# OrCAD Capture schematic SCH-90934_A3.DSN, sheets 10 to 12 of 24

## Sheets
10 C-14 ENET1: size C
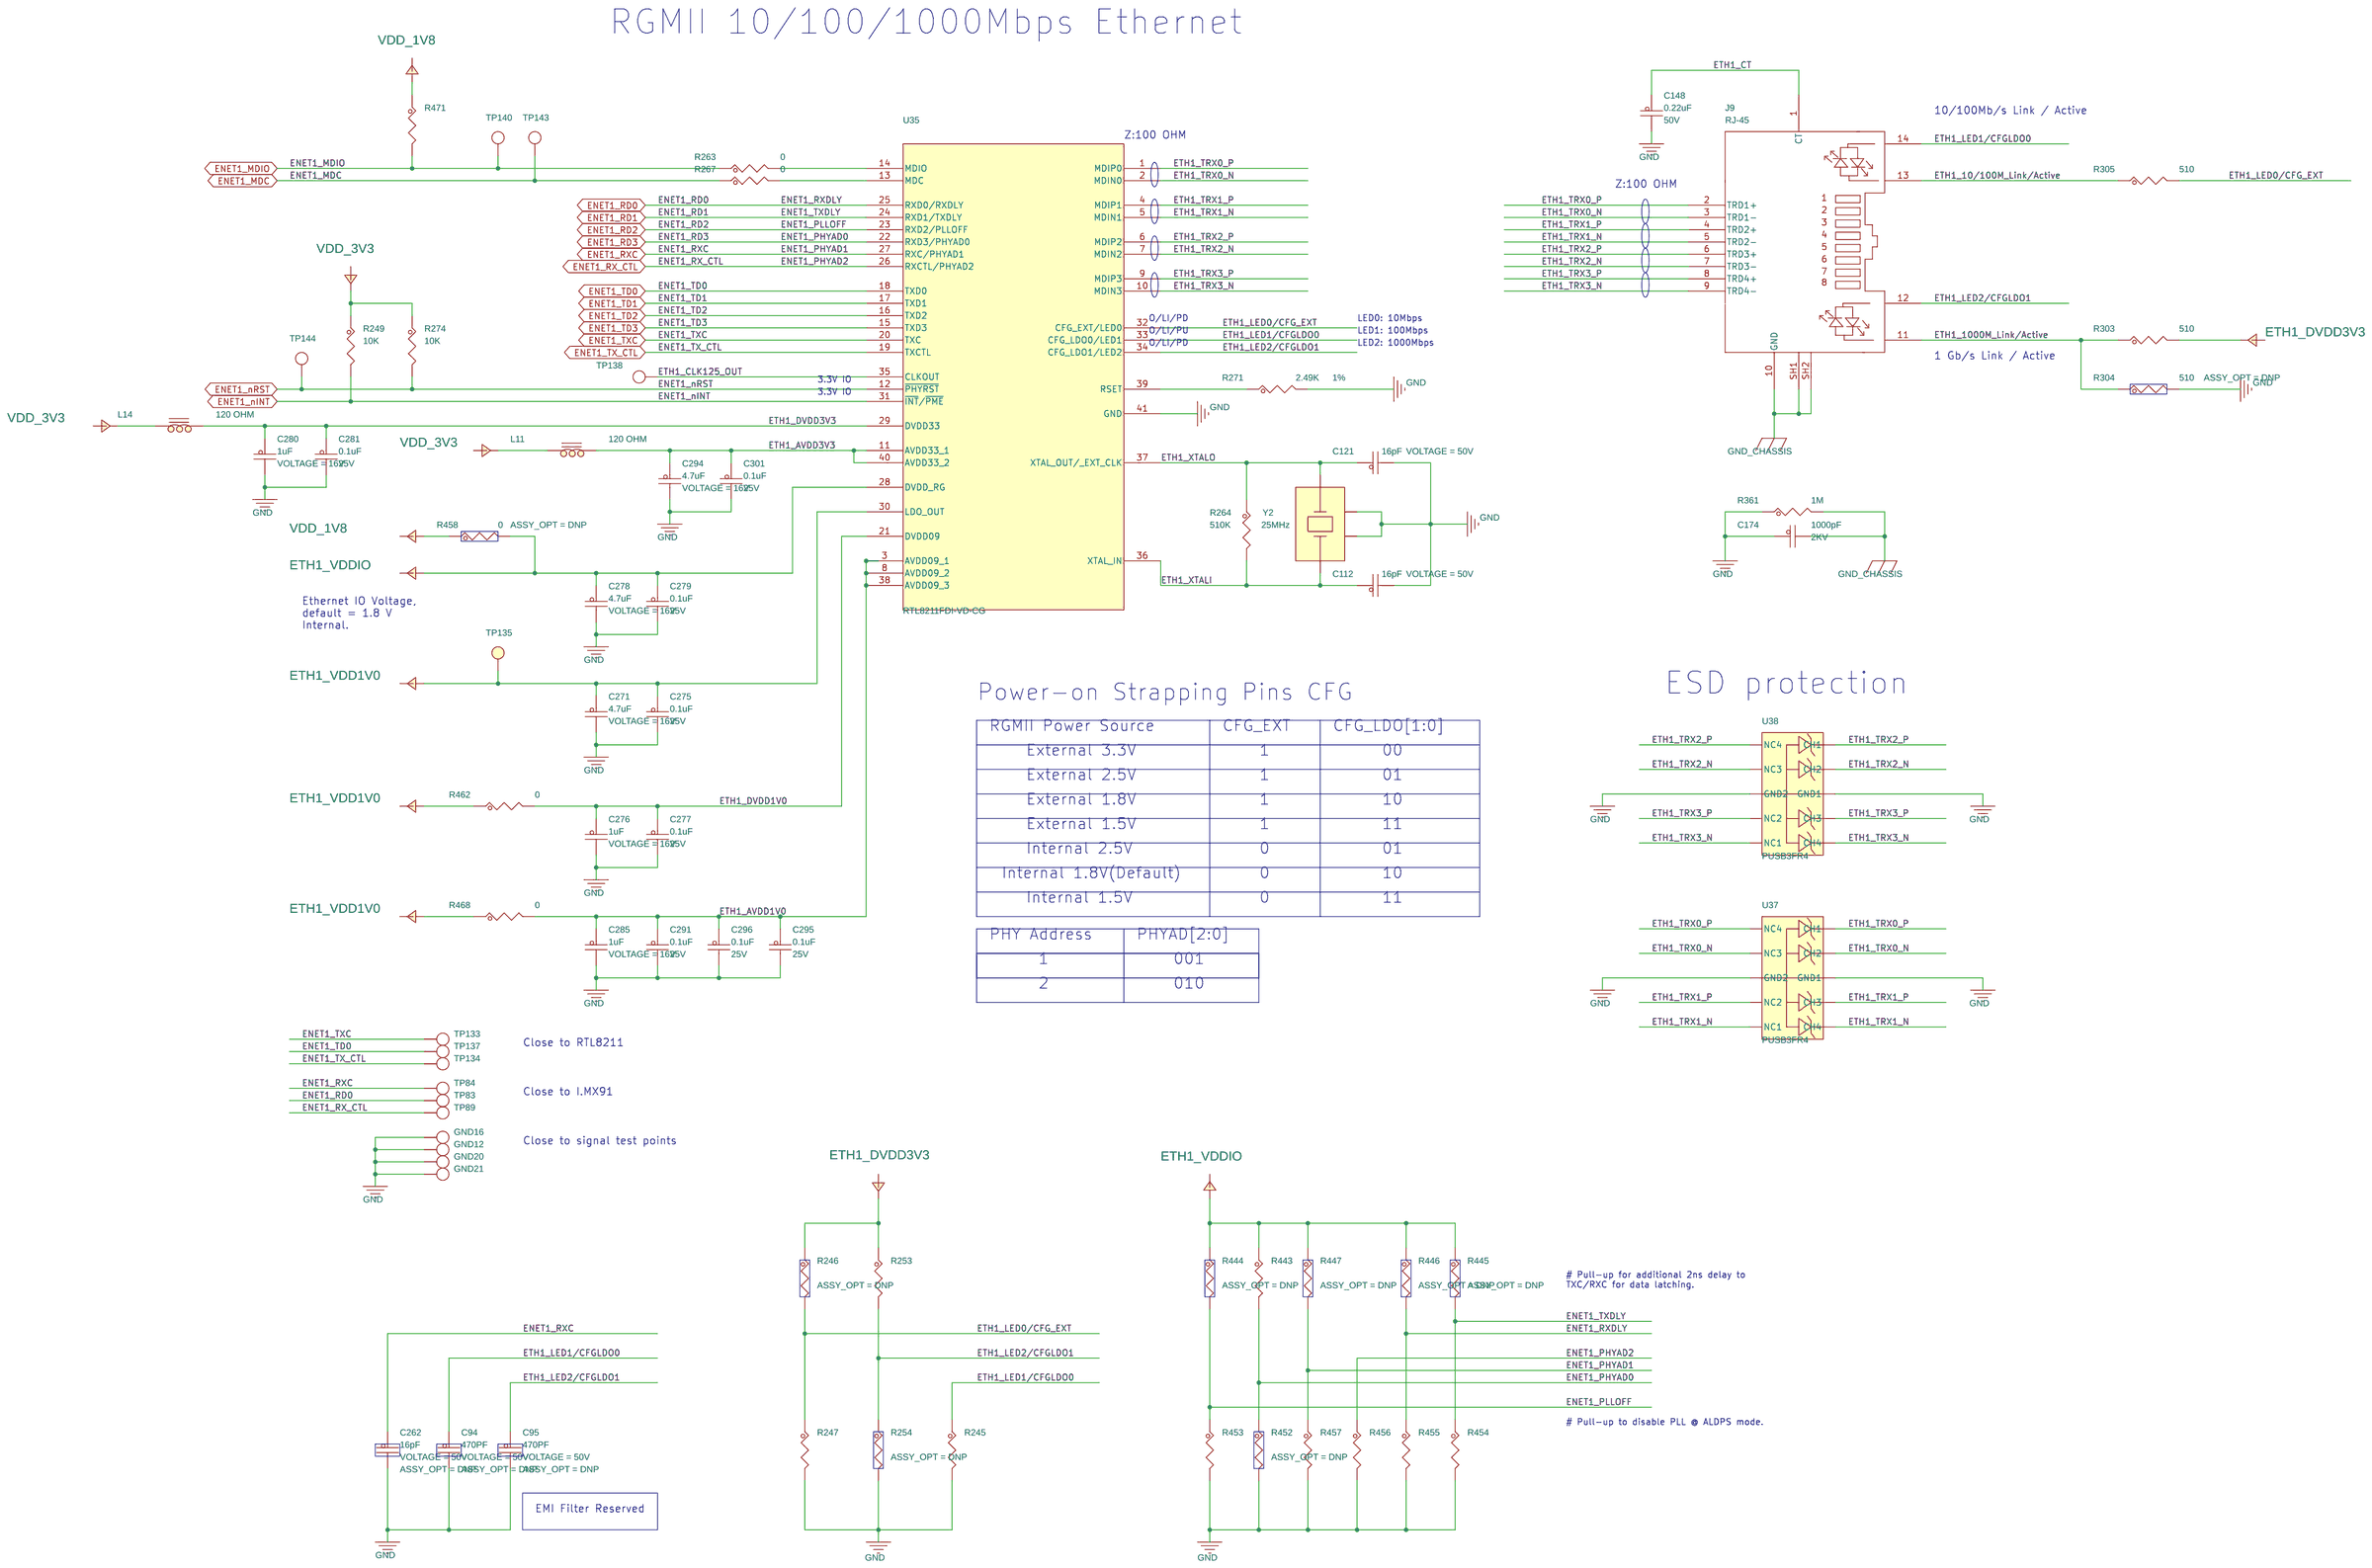
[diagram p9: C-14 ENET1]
11 C-13 USB1 TYPE-C: size C
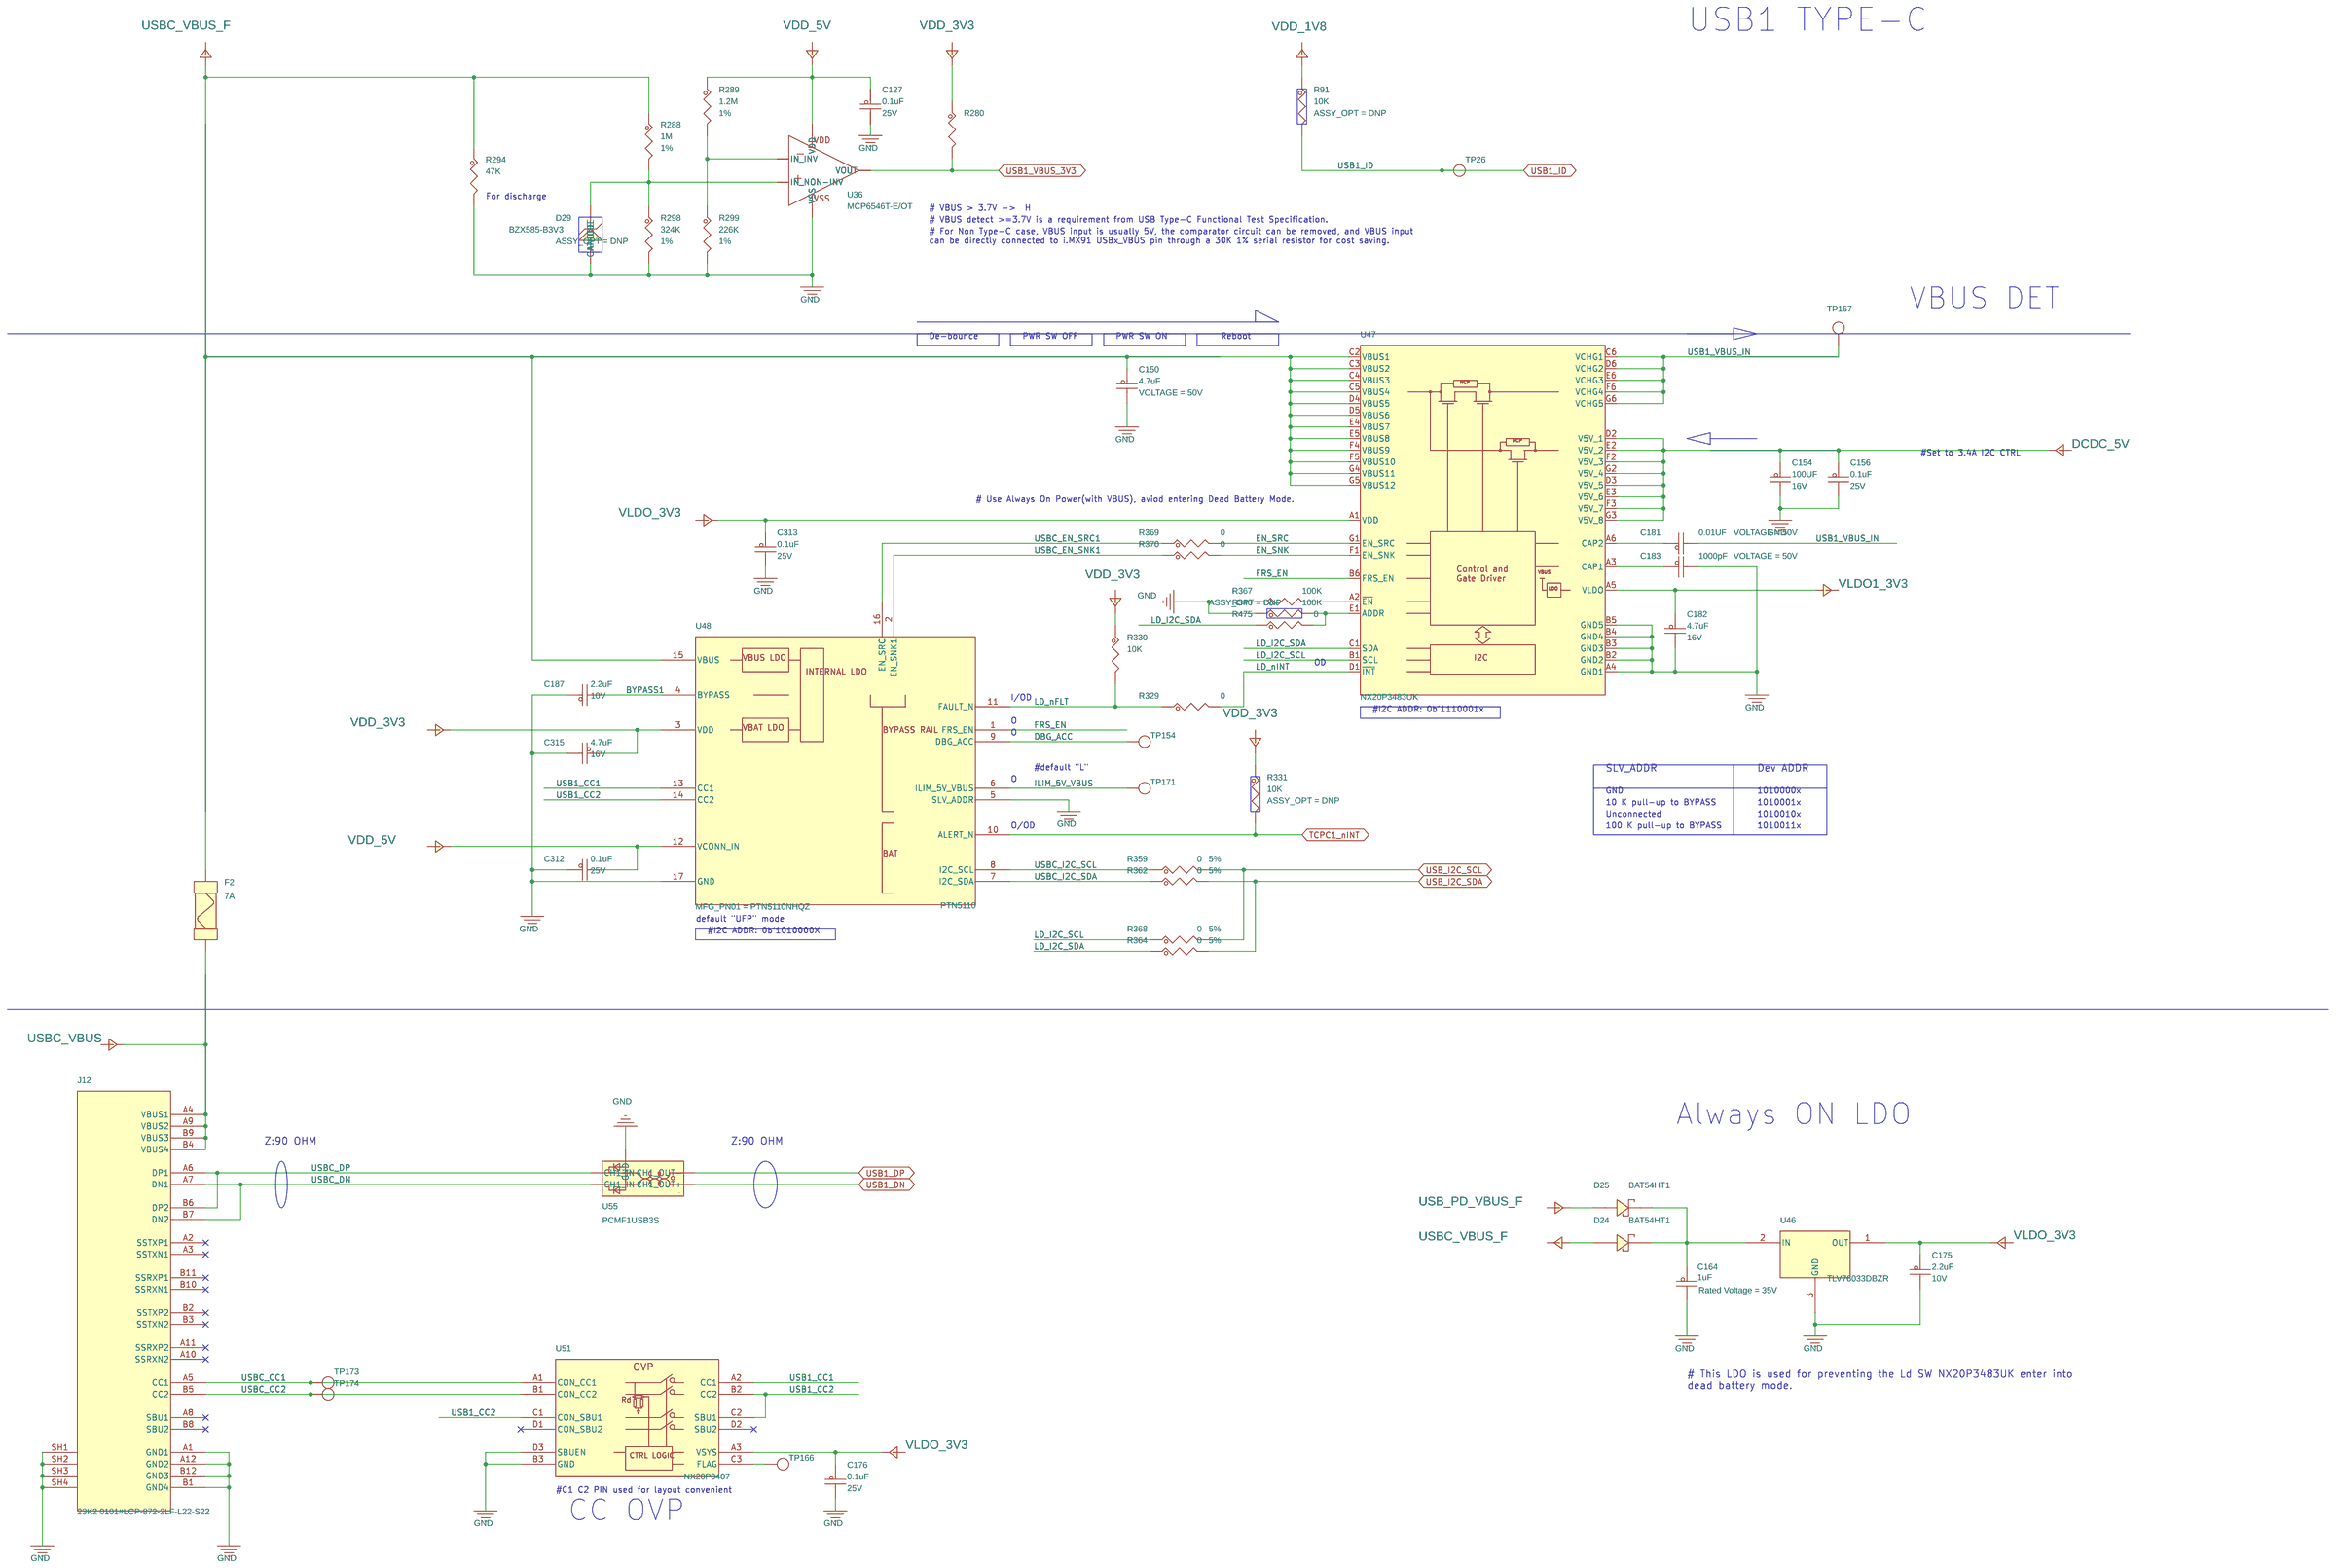
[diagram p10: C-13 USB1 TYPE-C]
12 C-12 SYSTEM POWER: size A2
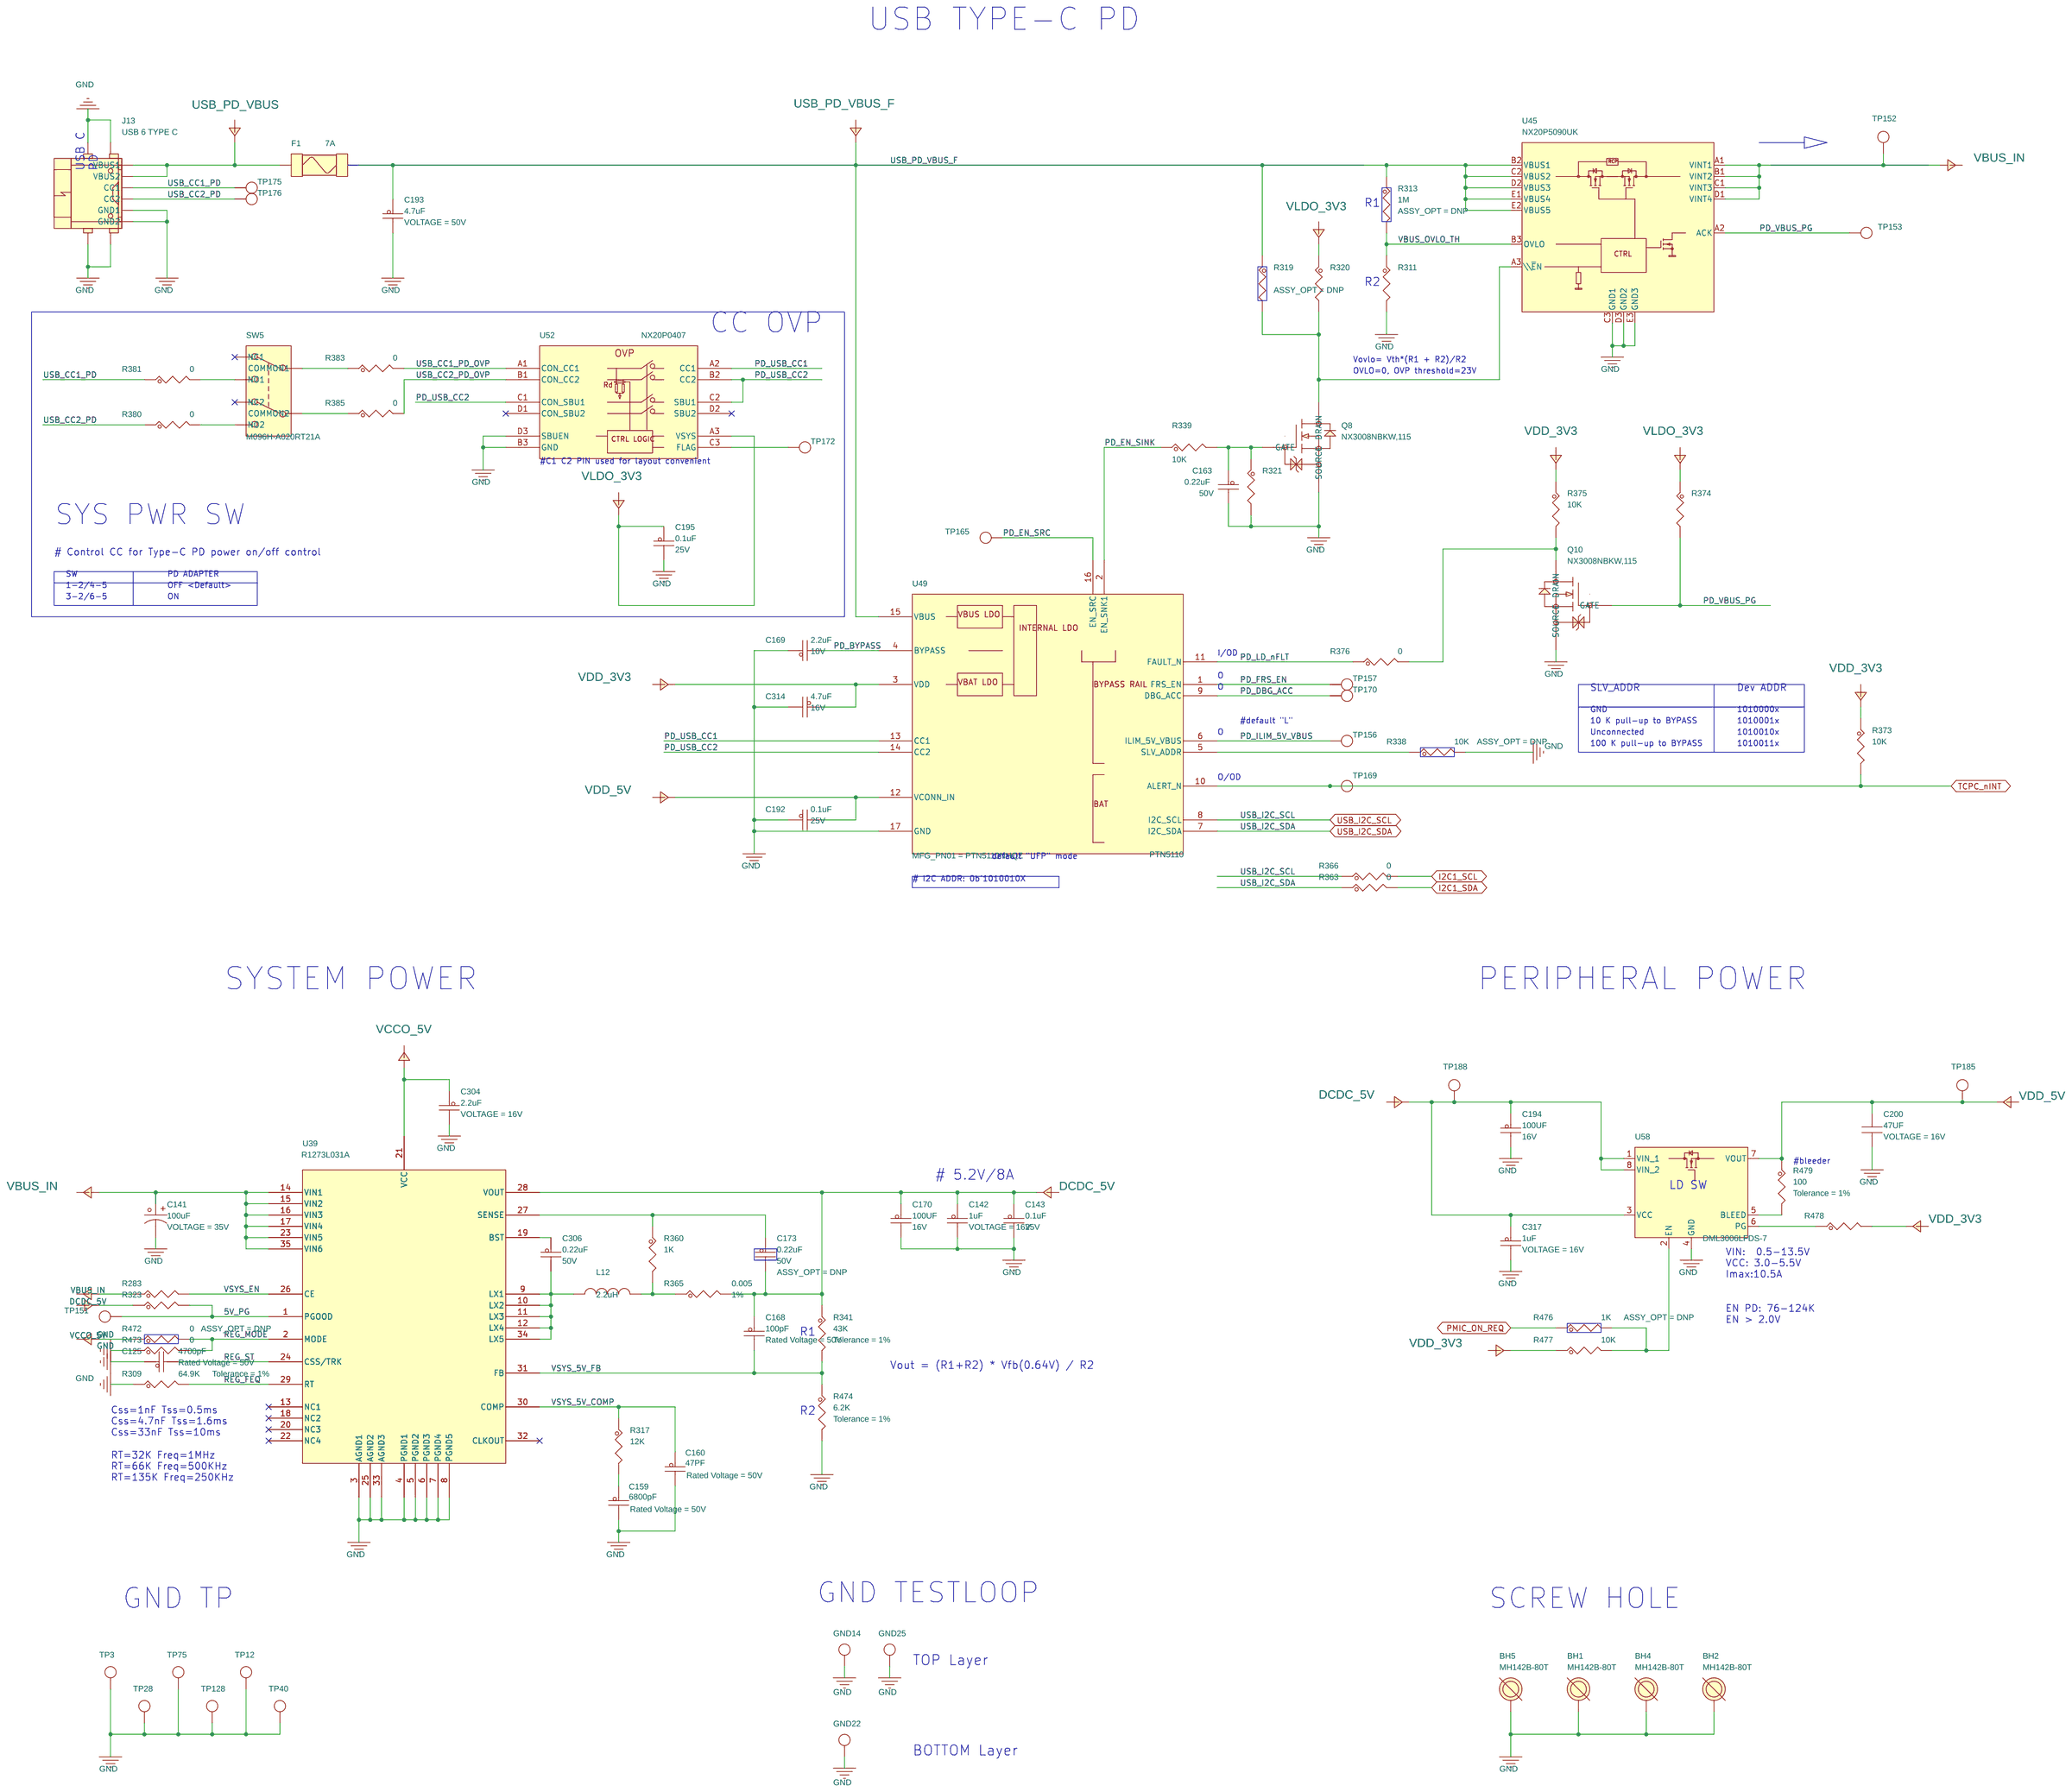
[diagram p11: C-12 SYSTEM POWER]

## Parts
sheet C-12 SYSTEM POWER
BH1  MH142B-80T  [mh142p080]
BH2  MH142B-80T  [mh142p080]
BH4  MH142B-80T  [mh142p080]
BH5  MH142B-80T  [mh142p080]
C125  4700pF  [CC0402_25]
C141  100uF  [case_d_al]
C142  1uF  [CC0402_25]
C143  0.1uF  [CC0402_25]
C159  6800pF  [cc0402_tol0p15]
C160  47PF  [CC0402_25]
C163  0.22uF  [CC0402_25]
C168  100pF  [CC0402_25]
C169  2.2uF  [CC0402_25]
C170  100UF  [1210_CC]
C173  0.22uF  [CC0402_25]
C192  0.1uF  [CC0402_25]
C193  4.7uF  [CC1210]
C194  100UF  [1210_CC]
C195  0.1uF  [CC0402_25]
C200  47UF  [1210_CC]
C304  2.2uF  [CC0603_OV]
C306  0.22uF  [CC0402_25]
C314  4.7uF  [cc0402_tol0p15]
C317  1uF  [CC0402_25]
F1  7A  [fuse_3p4x1p8]
GND14  TESTLOOP  [TEST_PIN_TP107]
GND22  TESTLOOP  [TEST_PIN_TP107]
GND25  TESTLOOP  [TEST_PIN_TP107]
J13  USB 6 TYPE C  [usb6p_typec_ra_sm]
L12  2.2uH  [ind2_7p3x6p8_sm]
Q8  NX3008NBKW,115  [sc70_3]
Q10  NX3008NBKW,115  [sc70_3]
R283  100K  [0402_CC]
R309  64.9K  [RC0402_25]
R311  100K  [0402_CC]
R313  1M  [0402_CC]
R317  12K  [RC0402_25]
R319  100K  [0402_CC]
R320  100K  [0402_CC]
R321  100K  [0402_CC]
R323  100K  [0402_CC]
R338  10K  [0402_CC]
R339  10K  [0402_CC]
R341  43K  [0402_CC]
R360  1K  [0402_CC]
R363  0  [0402_CC]
R365  0.005  [1206_CC]
R366  0  [0402_CC]
R373  10K  [0402_CC]
R374  100K  [0402_CC]
R375  10K  [0402_CC]
R376  0  [0402_CC]
R380  0  [0402_CC]
R381  0  [0402_CC]
R383  0  [0402_CC]
R385  0  [0402_CC]
R472  0  [0402_CC]
R473  0  [0402_CC]
R474  6.2K  [RC0402_25]
R476  1K  [0402_CC]
R477  10K  [0402_CC]
R478  100K  [0402_CC]
R479  100  [RC0805_OV]
SW5  M096H-A020RT21A  [sw6_dpdt_m096h_th]
TP3  TPAD_050  [TPAD_050]
TP12  TPAD_050  [TPAD_050]
TP28  TPAD_050  [TPAD_050]
TP40  TPAD_050  [TPAD_050]
TP75  TPAD_050  [TPAD_050]
TP128  TPAD_050  [TPAD_050]
TP151  TPAD_020  [tpad_020]
TP152  TPAD_050  [TPAD_050]
TP153  TPAD_020  [tpad_020]
TP156  TPAD_020  [tpad_020]
TP157  TPAD_020  [tpad_020]
TP165  TPAD_020  [tpad_020]
TP169  TPAD_020  [tpad_020]
TP170  TPAD_020  [tpad_020]
TP172  TPAD_020  [tpad_020]
TP175  TPAD_020  [tpad_020]
TP176  TPAD_020  [tpad_020]
TP185  TPAD_050  [TPAD_050]
TP188  TPAD_050  [TPAD_050]
U39  R1273L031A  [qfn0505-32b_0p5]
U45  NX20P5090UK  [wlcsp15_0p5_1p57x2p59]
U49  PTN5110  [hx2qfn16_0p4_2p7x2p7]
U52  NX20P0407  [wlcsp12_0p4_1p3x1p7mm_smdp]
U58  DML3006LFDS-7  [dfn2020_0p5_sq2]
sheet C-13 USB1 TYPE-C
C127  0.1uF  [CC0402_25]
C150  4.7uF  [CC1210]
C154  100UF  [1210_CC]
C156  0.1uF  [CC0402_25]
C164  1uF  [CC0603_OV]
C175  2.2uF  [CC0402_25]
C176  0.1uF  [CC0402_25]
C181  0.01UF  [CC0402_25]
C182  4.7uF  [cc0402_tol0p15]
C183  1000pF  [CC0402_25]
C187  2.2uF  [CC0402_25]
C312  0.1uF  [CC0402_25]
C313  0.1uF  [CC0402_25]
C315  4.7uF  [cc0402_tol0p15]
D24  BAT54HT1  [SOD323]
D25  BAT54HT1  [SOD323]
D29  BZX585-B3V3  [sod523]
F2  7A  [fuse_3p4x1p8]
J12  23K2 0101#LCP-872-2LF-L22-S22  [con24_usb_typec_ra_smt_th_2p2l]
R91  10K  [0402_CC]
R280  1K  [0402_CC]
R288  1M  [0402_CC]
R289  1.2M  [0402_CC]
R294  47K  [0603_CC]
R298  324K  [0402_CC]
R299  226K  [0402_CC]
R329  0  [0402_CC]
R330  10K  [0402_CC]
R331  10K  [0402_CC]
R340  100K  [0402_CC]
R359  0  [0402_CC]
R362  0  [0402_CC]
R364  0  [0402_CC]
R367  100K  [0402_CC]
R368  0  [0402_CC]
R369  0  [0402_CC]
R370  0  [0402_CC]
R475  0  [0402_CC]
TP26  TPAD_020  [tpad_020]
TP154  TPAD_020  [tpad_020]
TP166  TPAD_020  [tpad_020]
TP167  TPAD_050  [TPAD_050]
TP171  TPAD_020  [tpad_020]
TP173  TPAD_020  [tpad_020]
TP174  TPAD_020  [tpad_020]
U36  MCP6546T-E/OT  [SOT-23-5]
U46  TLV76033DBZR  [SOT-23]
U47  NX20P3483UK  [wlcsp42_0p4_2p94x2p54_smdp]
U48  PTN5110  [hx2qfn16_0p4_2p7x2p7]
U51  NX20P0407  [wlcsp12_0p4_1p3x1p7mm_smdp]
U55  PCMF1USB3S  [wlcsp5_0p4_0p82x1p22]
sheet C-14 ENET1
C94  470PF  [CC0402_25]
C95  470PF  [CC0402_25]
C112  16pF  [CC0402_25]
C121  16pF  [CC0402_25]
C148  0.22uF  [CC0402_25]
C174  1000pF  [1206_CC]
C262  16pF  [CC0402_25]
C271  4.7uF  [cc0402_tol0p15]
C275  0.1uF  [CC0402_25]
C276  1uF  [CC0402_25]
C277  0.1uF  [CC0402_25]
C278  4.7uF  [cc0402_tol0p15]
C279  0.1uF  [CC0402_25]
C280  1uF  [CC0402_25]
C281  0.1uF  [CC0402_25]
C285  1uF  [CC0402_25]
C291  0.1uF  [CC0402_25]
C294  4.7uF  [cc0402_tol0p15]
C295  0.1uF  [CC0402_25]
C296  0.1uF  [CC0402_25]
C301  0.1uF  [CC0402_25]
GND12  TPAD_020  [tpad_020]
GND16  TPAD_020  [tpad_020]
GND20  TPAD_020  [tpad_020]
GND21  TPAD_020  [tpad_020]
J9  RJ-45  [con_rj45_10_2led_th]
L11  120 OHM  [IND_0603]
L14  120 OHM  [IND_0603]
R245  4.7K  [RC0402_25]
R246  4.7K  [RC0402_25]
R247  4.7K  [RC0402_25]
R249  10K  [0402_CC]
R253  4.7K  [RC0402_25]
R254  4.7K  [RC0402_25]
R263  0  [0402_CC]
R264  510K  [0402_CC]
R267  0  [0402_CC]
R271  2.49K  [0402_CC]
R274  10K  [0402_CC]
R303  510  [0402_CC]
R304  510  [0402_CC]
R305  510  [0402_CC]
R361  1M  [1206_CC]
R443  4.7K  [RC0402_25]
R444  4.7K  [RC0402_25]
R445  4.7K  [RC0402_25]
R446  4.7K  [RC0402_25]
R447  4.7K  [RC0402_25]
R452  4.7K  [RC0402_25]
R453  4.7K  [RC0402_25]
R454  4.7K  [RC0402_25]
R455  4.7K  [RC0402_25]
R456  4.7K  [RC0402_25]
R457  4.7K  [RC0402_25]
R458  0  [0402_CC]
R462  0  [0603_CC]
R468  0  [0603_CC]
R471  1.5K  [0402_CC]
TP83  TPAD_020  [tpad_020]
TP84  TPAD_020  [tpad_020]
TP89  TPAD_020  [tpad_020]
TP133  TPAD_020  [tpad_020]
TP134  TPAD_020  [tpad_020]
TP135  TP_35MIL  [testpoint_35mil]
TP137  TPAD_020  [tpad_020]
TP138  TPAD_020  [tpad_020]
TP140  TPAD_020  [tpad_020]
TP143  TPAD_020  [tpad_020]
TP144  TPAD_020  [tpad_020]
U35  RTL8211FDI-VD-CG  [qfn40_0p4_5x5mm]
U37  PUSB3FR4  [xson10_0p5_1p1x2p6mm]
U38  PUSB3FR4  [xson10_0p5_1p1x2p6mm]
Y2  25MHz  [xtl4_2p5x2mm_sm]

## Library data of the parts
BH1 BH2 BH4 BH5 = MOUNT_HOLE: MOUNTING HOLE DRILL 80MIL PAD 142MIL PLATED TH NO PART TO ORDER; AGILE_PN: 280-77354; CAD_APPROVED: Yes; HEIGHT: 0.1MM; ROHS: Yes
C125 = CAP_NP: CAP CER 4700pF 50V 10% X7R AEC-Q200 0402; AGILE_PN: 150-79034; CAD_APPROVED: Yes; FPLIST: CC0402_25,CC0402_HD,0402_CC,capc0402_l; HEIGHT: 0.55MM; MFG_NAME01: MURATA; MFG_PN01: GCM155R71H472KA37D; Package Size: 0402; ROHS: Yes; Rated Voltage: 50V; Temp Range: -55C to +125C; Tolerance: 10%
C141 = CAP_POL: CAP ALEL 100uF 35V 20% AEC-Q200 SMT; AGILE_PN: 150-80610; CAD_APPROVED: Yes; HEIGHT: 6.1mm; MFG_NAME01: PANASONIC; MFG_PN01: EEEFT1V101AP; Package Type: SMT; ROHS: Yes; Rated Voltage: 35V; Temp Range: -55C to +150C; Tolerance: 20%; VOLTAGE: 35V
C142 C317 = CAP_NP: CAP CER 1uF 16V 10% X5R 0402; AGILE_PN: 150-78973; CAD_APPROVED: Yes; FPLIST: CC0402_25,CC0402_HD,0402_CC,capc0402_l; HEIGHT: 0.55 MM; MFG_NAME01: TDK; MFG_PN01: C1005X5R1C105K; ROHS: Yes; Rated Voltage: 16V; Temp Range: -55C to +85C; Tolerance: 10%; VOLTAGE: 16V; voltage rating: 16V
C127 C143 C156 C176 C192 C195 C275 C277 C279 C281 C291 C295 C296 C301 C312 C313 = CAP_NP: CAP CER 0.1UF 25V 10% X5R 0402; AGILE_PN: 150-78633; CAD_APPROVED: Yes; FPLIST: CC0402_25,CC0402_HD,0402_CC,capc0402_l; HEIGHT: 0.55MM; MFG_NAME01: YAGEO AMERICA; MFG_PN01: CC0402KRX5R8BB104; Package Size: 0402; ROHS: Yes; Rated Voltage: 25V; Temp Range: -55C to +85C; Tolerance: 10%; VOLTAGE: 25V
C159 = CAP_NP: CAP CER 6800PF 50V 5% C0G 0402; AGILE_PN: 150-80807; CAD_APPROVED: Yes; FPLIST: cc0402_tol0p15,cc0402_tol0p15_ov,0402_cc_nsp; HEIGHT: 0.65MM; MFG_NAME01: MURATA; MFG_PN01: GRM1555C1H682JE01; Package Size: 0402; Package Type: Surface Mount; Rated Voltage: 50V; Temp Range: -55C to +125C; Tolerance: 5%
C160 = CAP_NP: CAP CER 47PF 50V 5% C0G 0402; AGILE_PN: 150-75169; CAD_APPROVED: Yes; FPLIST: CC0402_25,CC0402_HD,0402_CC,capc0402_l; HEIGHT: 0.64 MM; MFG_NAME01: CAL-CHIP; MFG_PN01: GMC04CG470J50NT-LF; ROHS: Yes; Rated Voltage: 50V; Temp Range: -55C to +125C; Tolerance: 5%
C163 = CAP_NP: CAP CER 0.22uF 50V 10% X5R 0402; AGILE_PN: 150-79999; CAD_APPROVED: Yes; FPLIST: CC0402_25,CC0402_HD,0402_CC; HEIGHT: 0.55MM; MFG_NAME01: TAIYO YUDEN; MFG_PN01: UMK105BJ224KV-F; Package Size: 0402; ROHS: Yes; Rated Voltage: 50V; Temp Range: -55C to +85C; Temp_Range: -55°C to +85°C; Tolerance: 10%; VOLTAGE: 50V
C168 = CAP_NP: CAP CER 100PF 50V 5% C0G 0402; AGILE_PN: 150-79170; CAD_APPROVED: Yes; FPLIST: CC0402_25,CC0402_HD,0402_CC,capc0402_l; HEIGHT: 0.55MM; MFG_NAME01: AVX; MFG_PN01: 04025A101JAT2A; ROHS: Yes; Rated Voltage: 50V; Temp Range: -55C to +125C; Tolerance: 5%; VOLTAGE: 50V
C169 C175 C187 = CAP_NP: CAP CER 2.2uF 10V 10% X5R 0402; AGILE_PN: 150-78974; CAD_APPROVED: Yes; FPLIST: CC0402_25,CC0402_HD,0402_CC,capc0402_l; HEIGHT: 0.55 MM; MFG_NAME01: TDK; MFG_PN01: C1005X5R1A225K; Package Size: 0402; ROHS: Yes; Rated Voltage: 10V; Temp Range: -55C to +85C; Tolerance: 10%; VOLTAGE: 10V
C154 C170 C194 = CAP_NP: CAP CER 100uF 16V 20% X5R 1210; AGILE_PN: 150-79142; CAD_APPROVED: Yes; FPLIST: CC1210,1210_CC; HEIGHT: 2.8MM; MFG_NAME01: KYOCERA; MFG_PN01: 1210YD107MAT2A; Package Size: 1210; ROHS: Yes; Rated Voltage: 16V; Temp Range: -55C to +85C; Tolerance: 20%; VOLTAGE: 16V
C173 = CAP_NP: CAP CER 0.22uF 50V 10% X5R 0402; AGILE_PN: 150-79999; ASSY_OPT: DNP; CAD_APPROVED: Yes; FPLIST: CC0402_25,CC0402_HD,0402_CC,capc0402_l; HEIGHT: 0.55MM; MFG_NAME01: TAIYO YUDEN; MFG_PN01: UMK105BJ224KV-F; Package Size: 0402; ROHS: Yes; Rated Voltage: 50V; Temp Range: -55C to +85C; Temp_Range: -55°C to +85°C; Tolerance: 10%; VOLTAGE: 50V
C150 C193 = CAP_NP: CAP CER 4.7UF 50V 10% X7R 1210; AGILE_PN: 150-76570; CAD_APPROVED: Yes; FPLIST: CC1210,1210_CC; HEIGHT: 2.7MM; MFG_NAME01: YAGEO AMERICA; MFG_PN01: CC1210KKX7R9BB475; ROHS: Yes; Rated Voltage: 50V; Temp Range: -55C to +125C; Tolerance: 10%; VOLTAGE: 50V
C200 = MOT_CAP: CAP CER 47UF 16V 10% X5R 1210; AGILE_PN: 150-75908; CAD_APPROVED: Yes; FPLIST: CC1210,1210_CC; HEIGHT: 2.7 mm; MFG_NAME01: YAGEO AMERICA; MFG_PN01: CC1210KKX5R7BB476; ROHS: Yes; Rated Voltage: 16V; Temp Range: -55C to +85C; Tolerance: 10%; VOLTAGE: 16V
C304 = CAP_NP: CAP CER 2.2UF 16V 10% X5R 0603; AGILE_PN: 150-75417; CAD_APPROVED: YES; FPLIST: CC0603_OV,CC0603,0603_CC,cc0603_0402_nsp; HEIGHT: 0.9 MM; MFG_NAME01: CAPAX TECHNOLOGIES INC.; MFG_PN01: 0603B225K160SNT; Package Size: 0603; ROHS: Yes; Rated Voltage: 16V; Temp Range: -55C to +85C; Tolerance: 10%; VOLTAGE: 16V
C306 = CAP_NP: CAP CER 0.22uF 50V 10% X5R 0402; AGILE_PN: 150-79999; CAD_APPROVED: Yes; FPLIST: CC0402_25,CC0402_HD,0402_CC,capc0402_l; HEIGHT: 0.55MM; MFG_NAME01: TAIYO YUDEN; MFG_PN01: UMK105BJ224KV-F; Package Size: 0402; ROHS: Yes; Rated Voltage: 50V; Temp Range: -55C to +85C; Temp_Range: -55°C to +85°C; Tolerance: 10%; VOLTAGE: 50V
C182 C271 C278 C294 C314 C315 = CAP_NP: CAP CER 4.7uF 10V 10% X5R 0402; AGILE_PN: 150-80044; CAD_APPROVED: Yes; FPLIST: CC0603_OV,CC0603,cc0603_0805_nsp,0603_CC_NSP; HEIGHT: 0.65MM; MFG_NAME01: SAMSUNG ELECTRO MECHANICS; MFG_PN01: CL05A475KP5NRNC; ROHS: Yes; Rated Voltage: 10V; Temp Range: -55C to +85C; Tolerance: 10%; VOLTAGE: 16V
F1 F2 = FUSE: FUSE HIGH I2T 7A 32V 1206; 3D_Mechanical_Footprint_File: http://fcl.am.freescale.net/ALLEGRO/step/fuse_3p4x1p8_34h.STEP; AGILE_PN: 510-77913; CAD_APPROVED: Yes; HEIGHT: 0.8639; MFG_NAME01: LITTELFUSE; MFG_PN01: 0440007.WR; ROHS: Yes
GND14 GND22 GND25 = TestLoop: TEST POINT PAD SIZE 4.7MM X 3.5MM SN; 3D_Mechanical_Footprint_File: http://fcl.am.freescale.net/ALLEGRO/step/TEST_PIN_TP107.STEP; AGILE_PN: 211-30043; CAD_APPROVED: Yes; HEIGHT: 2.286MM; MFG_NAME01: KEYSTONE ELECTRONICS; MFG_PN01: 5016; ROHS: Yes; Temp Range: -50°C to +146°C
J13 = USB6_TYPEC_SH4_1_A: CON 6 USB TYPE C PWR SHLD RA SMT 1MM SP  187H AU; 3D_Mechanical_Footprint_File: http://fcl.am.freescale.net/ALLEGRO/step/usb6p_typec_ra_sm.STEP; AGILE_PN: 211-81576; CAD_APPROVED: Yes; HEIGHT: 4.76; MFG_NAME01: FODOT ELECTRONICS CO.,LTD.; MFG_PN01: WT07FS-06GAA-A70BC32; Package Type: SMD/SMT; ROHS: Yes; Temp Range: -25°C to +85°C
L12 = IND: IND PWR 2.2uH@100kHz 8A 20% SMD; 3D_Mechanical_Footprint_File: http://fcl.am.freescale.net/ALLEGRO/step/ind2_7x7.STEP; AGILE_PN: 180-10044; CAD_APPROVED: Yes; HEIGHT: 3; MFG_NAME01: SHENZHEN SUNLORD ELECTRONICS CO., LTD; MFG_PN01: MWSA0603S-2R2MT; ROHS: Yes; Temp Range: -55°C ~ 125°C
Q8 Q10 = NX3008NBKW_SOT323: TRAN NMOS SW 30V 350mA AEC-Q101 SC-70; 3D_Mechanical_Footprint_File: http://fcl.am.freescale.net/ALLEGRO/step/sc70_3.STEP; AGILE_PN: 480-79736; CAD_APPROVED: Yes; HEIGHT: 1.1; MFG_NAME01: NEXPERIA; ROHS: Yes
R283 R311 R320 R321 R323 R367 R374 R478 = RES: RES MF 100K 1/16W 5% 0402; AGILE_PN: 470-75597; CAD_APPROVED: Yes; FPLIST: RC0402_25,RC0402_HD,0402_CC; HEIGHT: 0.40 MM; MFG_NAME01: VENKEL COMPANY; MFG_PN01: CR0402-16W-104JT; ROHS: Yes; Temp Range: -55C to +155C; Temp_Range: -55C to +155C; Tolerance: 5%; VOLTAGE: 50V
R309 = RES: RES MF 64.9K  1/16W 1% 0402; AGILE_PN: 470-31040; CAD_APPROVED: Yes; FPLIST: RC0402_25,RC0402_HD,0402_CC; HEIGHT: 0.40 MM; MFG_NAME01: YAGEO AMERICA; MFG_PN01: RC0402FR-0764K9L; ROHS: Yes; Temp Range: -55°C ~ 155°C; Tolerance: 1%
R313 = RES: RES MF 1M 1/16W 1% 0402; AGILE_PN: 470-80575; ASSY_OPT: DNP; CAD_APPROVED: Yes; FPLIST: RC0402_25,RC0402_HD,0402_CC; HEIGHT: 0.4MM; MFG_NAME01: BOURNS; MFG_PN01: CR0402-FX-1004GLF; ROHS: Yes; Tolerance: 1%
R317 = RES: RES MF 12K 1/10W 5% 0402; AGILE_PN: 470-77303; CAD_APPROVED: Yes; FPLIST: RC0402_25,RC0402_HD,0402_CC; HEIGHT: 0.4MM; MFG_NAME01: PANASONIC; MFG_PN01: ERJ-2GEJ123X; ROHS: Yes; Tolerance: 5%
R319 R340 = RES: RES MF 100K 1/16W 5% 0402; AGILE_PN: 470-75597; ASSY_OPT: DNP; CAD_APPROVED: Yes; FPLIST: RC0402_25,RC0402_HD,0402_CC; HEIGHT: 0.40 MM; MFG_NAME01: VENKEL COMPANY; MFG_PN01: CR0402-16W-104JT; ROHS: Yes; Temp Range: -55C to +155C; Temp_Range: -55C to +155C; Tolerance: 5%; VOLTAGE: 50V
R91 R331 R338 = RES: RES MF 10K 1/16W 5% 0402; AGILE_PN: 470-75557; ASSY_OPT: DNP; CAD_APPROVED: Yes; FPLIST: RC0402_25,RC0402_HD,0402_CC; HEIGHT: 0.4 MM; MFG_NAME01: VISHAY INTERTECHNOLOGY; MFG_PN01: CRCW040210K0JNED; ROHS: Yes; Tolerance: 5%
R249 R274 R330 R339 R373 R375 R477 = RES: RES MF 10K 1/16W 5% 0402; AGILE_PN: 470-75557; CAD_APPROVED: Yes; FPLIST: RC0402_25,RC0402_HD,0402_CC; HEIGHT: 0.4 MM; MFG_NAME01: VISHAY INTERTECHNOLOGY; MFG_PN01: CRCW040210K0JNED; ROHS: Yes; Tolerance: 5%
R341 = RES: RES MF 43.0K 1/16W 1% 0402; AGILE_PN: 470-77562; CAD_APPROVED: Yes; FPLIST: RC0402_25,RC0402_HD,0402_CC; HEIGHT: 0.4MM; MFG_NAME01: VISHAY INTERTECHNOLOGY; MFG_PN01: CRCW040243K0FKED; ROHS: Yes; Tolerance: 1%; VOLTAGE: 50V
R360 = RES: RES MF 1.0K 1/16W 5% 0402; AGILE_PN: 470-75555; CAD_APPROVED: Yes; FPLIST: RC0402_25,RC0402_HD,RC0402_X2,0402_CC,CAPC0402_L; HEIGHT: 0.41mm; MFG_NAME01: VISHAY INTERTECHNOLOGY; MFG_PN01: CRCW04021K00JNED; ROHS: Yes; Tolerance: 5%
R263 R267 R329 R359 R362-R364 R366 R368-R370 R376 R380 R381 R383 R385 R473 R475 = RES: RES MF ZERO OHM 1/16W 5% 0402; AGILE_PN: 470-75394; CAD_APPROVED: Yes; FPLIST: RC0402_25,RC0402_HD,RC0402_X2,0402_CC; HEIGHT: 0.45; MFG_NAME01: YAGEO AMERICA; MFG_PN01: RC0402JR-070RL; ROHS: Yes; Temp Range: -55 to +155C; Tolerance: 5%; VOLTAGE: 1/16W
R365 = RES: RES -- 0.005 OHM 1W 1% AEC-Q200 1206; AGILE_PN: 470-82436; CAD_APPROVED: Yes; FPLIST: RC1206_OV,RC1206,1206_CC; HEIGHT: 0.85; MFG_NAME01: CYNTEC; MFG_PN01: VSML1206S1-R005F; ROHS: Yes; Temp Range: -65°C ~ 170°C; Tolerance: 1%
R458 R472 = RES: RES MF ZERO OHM 1/16W 5% 0402; AGILE_PN: 470-75394; ASSY_OPT: DNP; CAD_APPROVED: Yes; FPLIST: RC0402_25,RC0402_HD,RC0402_X2,0402_CC; HEIGHT: 0.45; MFG_NAME01: YAGEO AMERICA; MFG_PN01: RC0402JR-070RL; ROHS: Yes; Temp Range: -55 to +155C; Tolerance: 5%; VOLTAGE: 1/16W
R474 = RES: RES MF 6.2K  1/16W 1% 0402; AGILE_PN: 470-30925; CAD_APPROVED: Yes; FPLIST: RC0402_25,RC0402_HD,0402_CC; HEIGHT: 0.40 MM; MFG_NAME01: YAGEO AMERICA; MFG_PN01: RC0402FR-076K2L; ROHS: Yes; Temp Range: - 55 C to + 155 C; Tolerance: 1%
R476 = RES: RES MF 1.0K 1/16W 5% 0402; AGILE_PN: 470-75555; ASSY_OPT: DNP; CAD_APPROVED: Yes; FPLIST: RC0402_25,RC0402_HD,RC0402_X2,0402_CC,CAPC0402_L; HEIGHT: 0.41mm; MFG_NAME01: VISHAY INTERTECHNOLOGY; MFG_PN01: CRCW04021K00JNED; ROHS: Yes; Tolerance: 5%
R479 = RES: RES MF 100 OHM 1/2W 1% AEC-Q200 0805; AGILE_PN: 470-80989; CAD_APPROVED: Yes; FPLIST: RC0805_OV,RC0805,0805_CC; HEIGHT: 0.7 MM; MFG_NAME01: PANASONIC; MFG_PN01: ERJ-P06F1000V; ROHS: Yes; Tolerance: 1%
SW5 = SW_DPDT_3: SW DPDT SLD 0.03A 50V TH; AGILE_PN: 510-78053; CAD_APPROVED: Yes; HEIGHT: 5.8MM; MFG_NAME01: FODOT ELECTRONICS CO.,LTD.; ROHS: Yes
TP3 TP12 TP28 TP40 TP75 TP128 TP152 TP167 TP185 TP188 = TESTLOOP: TEST POINT PAD 50MIL DIA SMT, NO PART TO ORDER; AGILE_PN: 211-76644; ASSY_OPT: DNP; CAD_APPROVED: Yes; HEIGHT: 0.1MM; MFG_NAME01: NOTACOMPONENT; MFG_PN01: NOTACOMPONENT; ROHS: Yes
GND12 GND16 GND20 GND21 TP26 TP83 TP84 TP89 TP133 TP134 TP137 TP138 TP140 TP143 TP144 TP151 TP153 TP154 TP156 TP157 TP165 TP166 TP169-TP176 = TESTLOOP: TEST POINT PAD 0.5MM DIA SMT, NO PART TO ORDER; AGILE_PN: 211-77484; ASSY_OPT: DNP; CAD_APPROVED: Yes; HEIGHT: 0.1MM; ROHS: Yes
U39 = R1273L031A: IC VREG SW BUCK 0.7-5.3V 14A 4-34V QFN32; AGILE_PN: 315-84277; CAD_APPROVED: Yes; HEIGHT: 0.85; MFG_NAME01: Nisshinbo Micro Devices Inc.; MFG_PN01: R1273L031A-E2-Y; Package Size: 5 x 5 mm; ROHS: Yes; Temp Range: -40°C to 105°C; VOLTAGE: 4-34V
U45 = NX20P5090UK_15P_A: IC USB PWR SW 5A 2.5-20V WLCSP15; 3D_Mechanical_Footprint_File: http://fcl.am.freescale.net/ALLEGRO/step/wlcsp15_0p5_1p57x2p59.STEP; AGILE_PN: 315-81116; CAD_APPROVED: Yes; HEIGHT: 0.595; MFG_NAME01: NXP SEMICONDUCTOR; MFG_PN01: NX20P5090UKAZ; ROHS: Yes; VOLTAGE: 2.5-20V
U48 U49 = PTN5110_QFN16: IC USB PD PHY 1PORT 2.7-5.5V HX2QFN16; 3D_Mechanical_Footprint_File: http://fcl.am.freescale.net/ALLEGRO/step/hx2qfn16_0p4_2p7x2p7.step; AGILE_PN: 315-81118; CAD_APPROVED: Yes; HEIGHT: 0.4; MFG_NAME01: NXP SEMICONDUCTOR; MFG_PN01: PTN5110NHQZ; ROHS: Yes; Temp Range: ¨C40C to +85C; Temp_Range: ¨C40C to +85C; VOLTAGE: 2.7-5.5V
U51 U52 = NX20P0407_WLCSP12_A: IC USB TYPE C PROTECTION +15KV/+8KV ESD WLCSP12; 3D_Mechanical_Footprint_File: http://fcl.am.freescale.net/ALLEGRO/step/wlcsp12_0p4_1p3x1p7mm_smdp.STEP; AGILE_PN: TMP-WF-31350; CAD_APPROVED: Yes; HEIGHT: 0.565 MM; MFG_NAME01: NXP SEMICONDUCTORS; PRE_APN: 312-81846; ROHS: Yes; Temp Range: -40C to +85C; VOLTAGE: +15KV/+8KV
U58 = DML3006LFDS-7_A: IC LOAD SW 0.5-13.5V 10.5A 3-5.5V DFN2020-8; 3D_Mechanical_Footprint_File: http://fcl.am.freescale.net/ALLEGRO/step/dfn2020_0p5_sq2.STEP; AGILE_PN: 315-83392; CAD_APPROVED: Yes; HEIGHT: 0.9; MFG_NAME01: DIODES INC; Package Size: 8-VFDFN Exposed Pad; ROHS: Yes; Supply Voltage: 3-5.5V; Temp Range: -40°C to +85°C; VOLTAGE: 3-5.5V
C164 = CAP_NP: CAP CER 1uF 35V 10% X7R 0603; AGILE_PN: 150-81157; CAD_APPROVED: Yes; FPLIST: CC0603_OV,CC0603,0603_CC; HEIGHT: 0.9MM; MFG_NAME01: TDK; MFG_PN01: C1608X7R1V105K080AC; Package Size: 0603 (1608 Metric); Package Type: Surface Mount, MLCC; ROHS: Yes; Rated Voltage: 35V; Temp Range: -55C to +125C; Tolerance: 10%
C181 = CAP_NP: CAP CER 0.01UF 50V 10% X7R 0402; AGILE_PN: 150-30114; CAD_APPROVED: Yes; FPLIST: CC0402_25,CC0402_HD,0402_CC,capc0402_l; HEIGHT: 0.55 MM; MFG_NAME01: MURATA; MFG_PN01: GRM155R71H103KA88D; ROHS: Yes; Rated Voltage: 50V; Temp Range: -55C to +125C; Tolerance: 10%; VOLTAGE: 50V
C183 = CAP_NP: CAP CER 1000PF 50V 5% C0G 0402; AGILE_PN: 150-76334; CAD_APPROVED: Yes; FPLIST: CC0402_25,CC0402_HD,0402_CC,capc0402_l; HEIGHT: 0.55MM; MFG_NAME01: MURATA; MFG_PN01: GRM1555C1H102JA01D; Package Size: 0402; Package Type: 180mm Paper Tape; ROHS: Yes; Rated Voltage: 50V; Temp Range: -55C to +125C; Tolerance: 5%; VOLTAGE: 50V
D24 D25 = DIODE_SCHTKY: DIODE SCH 30V 200MA -- SOD323; AGILE_PN: 480-30039; CAD_APPROVED: Yes; HEIGHT: 1.15; MFG_NAME01: ON SEMICONDUCTOR; MFG_PN01: BAT54HT1G
D29 = ZDIODE: DIODE ZNR 0.3W 3.3V 200mA AEC-Q101 SOD-523; AGILE_PN: 480-79870; ASSY_OPT: DNP; CAD_APPROVED: Yes; HEIGHT: 0.65; MFG_NAME01: NEXPERIA; ROHS: Yes; Temp Range: -65°C to +150°C; Temp_Range: -65°C to +150°C
J12 = USB24_TYPEC_SH4: CON 24 USB TYPE C RA SHLD HYBRID SMT-TH 0.5MM SP 145H AU 87L; AGILE_PN: 211-83409; CAD_APPROVED: Yes; HEIGHT: 3.67; MFG_NAME01: ANYTRONIC CORPORATION LIMITED; MFG_PN01: 23K20101#LCP-872-2LF-L22-S22; ROHS: Yes; Temp Range: -55°C to +105°C
R280 = RES: RES MF 1.0K 1/16W 5% 0402; AGILE_PN: 470-75555; CAD_APPROVED: Yes; FPLIST: RC0402_25,RC0402_HD,RC0402_X2,0402_CC,CAPC0402_L; HEIGHT: 0.41mm; MFG_NAME01: VISHAY INTERTECHNOLOGY; MFG_PN01: CRCW04021K00JNED; ROHS: Yes; TOL: 5%; Tolerance: 5%
R288 = RES: RES MF 1M 1/16W 1% 0402; AGILE_PN: 470-80575; CAD_APPROVED: Yes; FPLIST: RC0402_25,RC0402_HD,0402_CC; HEIGHT: 0.4MM; MFG_NAME01: BOURNS; MFG_PN01: CR0402-FX-1004GLF; ROHS: Yes; Tolerance: 1%
R289 = RES: RES MF 1.2M  1/10W 1% AEC-Q200 0402; AGILE_PN: 470-31182; CAD_APPROVED: Yes; FPLIST: RC0402_25,RC0402_HD,0402_CC; HEIGHT: 0.40 MM; MFG_NAME01: KOA SPEER; MFG_PN01: RK73H1ETTP1204F; ROHS: Yes; Temp Range: -55C to +155C; Temp_Range: -55C to +155C; Tolerance: 1%; VOLTAGE: 50V
R294 = RES: RES MF 47K 1/10W 5% 0603; AGILE_PN: 470-75849; CAD_APPROVED: Yes; FPLIST: RC0603_OV,RC0603,0603_CC; HEIGHT: 0.55 MM; MFG_NAME01: VENKEL COMPANY; MFG_PN01: CR0603-10W-473JT; ROHS: Yes; Tolerance: 5%
R298 = RES: RES MF 324K 1/16W 1% 0402; AGILE_PN: 470-76121; CAD_APPROVED: Yes; FPLIST: RC0402_25,RC0402_HD,0402_CC; HEIGHT: 0.40 MM; MFG_NAME01: PANASONIC; MFG_PN01: ERJ2RKF3243X; ROHS: Yes; Tolerance: 1%
R299 = RES: RES MF 226K 1/10W 1% AEC-Q200 0402; AGILE_PN: 470-31099; CAD_APPROVED: Yes; FPLIST: RC0402_25,RC0402_HD,0402_CC; HEIGHT: 0.40; MFG_NAME01: KOA SPEER; MFG_PN01: RK73H1ETTP2263F; ROHS: Yes; Temp Range: -55C to +155C; Tolerance: 1%
U36 = OPAMP_5P: IC COMP MICRO POWER RAIL-TO-RAIL 1.6-5.5V SOT23-5; 3D_Mechanical_Footprint_File: http://fcl.am.freescale.net/ALLEGRO/step/sot23-5.STEP; AGILE_PN: 315-10155; CAD_APPROVED: Yes; HEIGHT: 1.45 MM; MFG_NAME01: MICROCHIP TECHNOLOGY INC; ROHS: NULL; Temp Range: -40  °C to +125 °C; VOLTAGE: 1.6-5.5V
U46 = LM3480IM3: IC LIN VREG 3.3V 100mA 30V SOT23; AGILE_PN: 315-83524; CAD_APPROVED: Yes; HEIGHT: 1.12; MFG_NAME01: Texas Instruments; Package Size: SOT-23-3; ROHS: Yes; Temp Range: -40  °C - 125 °C
U47 = NX20P3483UK_42P: IC USB PD/TYPE-C PWR Sink/Source Combo SW 5A 2.8-20V WLCSP42; AGILE_PN: TMP-WF-32538; CAD_APPROVED: Yes; HEIGHT: 0.565MM; MFG_NAME01: NXP SEMICONDUCTORS; PRE_APN: 315-81752; ROHS: Yes; Temp Range: -40C to +85C; Temp_Range: -40C to +85C; VOLTAGE: 2.8-20V
U55 = PESD1USB30_5P: IC EMI FILTER ESD PROTECTION 15kV/LINE WLCSP5; 3D_Mechanical_Footprint_File: http://fcl.am.freescale.net/ALLEGRO/step/wlcsp5_0p4_0p82x1p22.STEP; AGILE_PN: 315-84061; CAD_APPROVED: Yes; HEIGHT: 0.6; MFG_NAME01: NEXPERIA; MFG_PN01: PCMF1USB3SZ; ROHS: Yes
C94 C95 = CAP_NP: CAP CER 470PF 50V 10% X7R 0402; AGILE_PN: 150-75452; ASSY_OPT: DNP; CAD_APPROVED: Yes; FPLIST: CC0402_25,CC0402_HD,0402_CC; HEIGHT: 0.55MM; MFG_NAME01: WALSIN TECHNOLOGY CORP.; MFG_PN01: 0402B471K500CT; PRIORITY_PN: 021-00340; ROHS: Yes; ROOM: RGMII_PHY; Rated Voltage: 50V; SIGNAL_MODEL: DEFAULT_CAPACITOR_470pF_2_1; Temp Range: -55C to +125C; Tolerance: 10%; VOLTAGE: 50V; WVDC: 50V
C112 C121 = CAP_NP: CAP CER 16pF 50V 1% C0G 0402; AGILE_PN: 150-80485; CAD_APPROVED: Yes; FPLIST: CC0402_25,CC0402_HD,0402_CC,capc0402_l; HEIGHT: 0.6MM; MFG_NAME01: AVX; MFG_PN01: 04025U160FAT2A; PRIORITY_PN: 021-00234; Package Size: 0402; ROHS: Yes; ROOM: RGMII_PHY; Rated Voltage: 50V; SIGNAL_MODEL: DEFAULT_CAPACITOR_22pF_2_1; Temp Range: -55C to +125C; Temp_Range: -55°C to 125°C; Tolerance: 1%; VOLTAGE: 50V; WVDC: 50V
C148 = CAP_NP: CAP CER 0.22uF 50V 10% X5R 0402; AGILE_PN: 150-79999; CAD_APPROVED: Yes; EN: 102-1-01816; FPLIST: CC0402_25,CC0402_HD,0402_CC,capc0402_l; HEIGHT: 0.55MM; MFG_NAME01: TAIYO YUDEN; MFG_PN01: UMK105BJ224KV-F; Package Size: 0402; ROHS: Yes; Rated Voltage: 50V; TOL: 10%; Temp Range: -55C to +85C; Tolerance: 10%; VOLTAGE: 50V
C174 = CAP_NP: CAP CER 1000pF 2KV 10% X7R 1206; AGILE_PN: 150-79462; CAD_APPROVED: Yes; FPLIST: CC1206_OV,CC1206,1206_CC; HEIGHT: 1.52MM; MFG_NAME01: AVX; MFG_PN01: 1206GC102KAT1A; Package Size: 1206; ROHS: Yes; Rated Voltage: 2000V (2KV); Temp Range: -55C to +125C; Tolerance: 10%; VOLTAGE: 2KV; WVDC: 2KV
C262 = CAP_NP: CAP CER 16pF 50V 1% C0G 0402; AGILE_PN: 150-80485; ASSY_OPT: DNP; CAD_APPROVED: Yes; FPLIST: CC0402_25,CC0402_HD,0402_CC,capc0402_l; HEIGHT: 0.6MM; MFG_NAME01: AVX; MFG_PN01: 04025U160FAT2A; PRIORITY_PN: 021-00234; Package Size: 0402; ROHS: Yes; ROOM: RGMII_PHY; Rated Voltage: 50V; SIGNAL_MODEL: DEFAULT_CAPACITOR_22pF_2_1; Temp Range: -55C to +125C; Temp_Range: -55°C to 125°C; Tolerance: 1%; VOLTAGE: 50V; WVDC: 50V
C276 C280 C285 = CAP_NP: CAP CER 1uF 16V 10% X5R 0402; AGILE_PN: 150-78973; CAD_APPROVED: Yes; FPLIST: CC0402_25,CC0402_HD,0402_CC,capc0402_l; HEIGHT: 0.55 MM; MFG_NAME01: TDK; MFG_PN01: C1005X5R1C105K; ROHS: Yes; Rated Voltage: 16V; SIGNAL_MODEL: DEFAULT_CAPACITOR_1e+06pF_2_1; TOL: 10%; Temp Range: -55C to +85C; Tolerance: 10%; VOLTAGE: 16V; voltage rating: 16V
J9 = RJ45_2_DUAL_LED_10P: CON 2X5 RJ-45 DUAL-LED SHLD RA TH 1.27MM SP 549H AU 120L; 3D_Mechanical_Footprint_File: http://fcl.am.freescale.net/ALLEGRO/step/con_rj45_10_2led_th.STEP; AGILE_PN: 210-81462; CAD_APPROVED: Yes; EN: 201-2-00061; HEIGHT: 13.95; MFG_NAME01: WURTH ELEKTRONIK EISOS GMBH & CO. KG (ELECTRONIC & ELECTROMEHANICAL COMP); MFG_PN01: 7499111446; ROHS: Yes; Temp Range: -40DegC to +85DegC; Temp_Range: -40DegC to +85DegC
L11 L14 = BEAD_0: IND FER BEAD 120OHM@100MHZ 2A 25% 0603; AGILE_PN: 180-78419; CAD_APPROVED: Yes; FPLIST: IND_0603,0603_CC; HEIGHT: 0.95; MFG_NAME01: MURATA; MFG_PN01: BLM18PG121SN1D; ROHS: Yes
R245 R247 R253 R443 R453-R457 = RES: RES MF 4.7K 1/16W 5% 0402; AGILE_PN: 470-75626; CAD_APPROVED: Yes; FPLIST: RC0402_25,RC0402_HD,0402_CC,RC0402_X2; HEIGHT: 0.41mm; MFG_NAME01: NIC COMPONENTS CORP; MFG_PN01: NRCL04J472TRF; ROHS: Yes; Tolerance: 5%
R246 R254 R444-R447 R452 = RES: RES MF 4.7K 1/16W 5% 0402; AGILE_PN: 470-75626; ASSY_OPT: DNP; CAD_APPROVED: Yes; FPLIST: RC0402_25,RC0402_HD,0402_CC,RC0402_X2; HEIGHT: 0.41mm; MFG_NAME01: NIC COMPONENTS CORP; MFG_PN01: NRCL04J472TRF; ROHS: Yes; Tolerance: 5%
R264 = RES: RES MF 510K 1/16W 5% 0402; AGILE_PN: 470-76166; CAD_APPROVED: Yes; FPLIST: RC0402_25,RC0402_HD,0402_CC; HEIGHT: 0.4 MM; MFG_NAME01: PANASONIC; MFG_PN01: ERJ-2GEJ514X; ROHS: Yes; Tolerance: 5%
R271 = RES: RES MF 2.49K  1/10W 1% AEC-Q200 0402; AGILE_PN: 470-30877; CAD_APPROVED: Yes; FPLIST: RC0402_25,RC0402_HD,0402_CC; HEIGHT: 0.40 MM; MFG_NAME01: KOA SPEER; MFG_PN01: RK73H1ETTP2491F; ROHS: Yes; SIGNAL_MODEL: DEFAULT_RESISTOR_2490OHM_2_1; Temp Range: -55C to +155C; Temp_Range: -55C to +155C; Tolerance: 1%; VOLTAGE: 50V
R303 R305 = RES: RES MF 510 OHM 1/16W 1% 0402; AGILE_PN: 470-80835; CAD_APPROVED: Yes; FPLIST: RC0402_25,RC0402_HD,0402_CC; HEIGHT: 0.4MM; MFG_NAME01: WALSIN TECHNOLOGY CORP.; MFG_PN01: WR04X5100FTL; ROHS: Yes; Tolerance: 1%
R304 = RES: RES MF 510 OHM 1/16W 1% 0402; AGILE_PN: 470-80835; ASSY_OPT: DNP; CAD_APPROVED: Yes; FPLIST: RC0402_25,RC0402_HD,0402_CC; HEIGHT: 0.4MM; MFG_NAME01: WALSIN TECHNOLOGY CORP.; MFG_PN01: WR04X5100FTL; ROHS: Yes; Tolerance: 1%
R361 = RES: RES MF 1.0M 1/4W 1% 1206; AGILE_PN: 470-81076; CAD_APPROVED: Yes; FPLIST: RC1206_OV,RC1206,1206_CC; HEIGHT: 0.6MM; MFG_NAME01: VISHAY INTERTECHNOLOGY; MFG_PN01: RCV12061M00FKEA; ROHS: Yes; Tolerance: 1%; VOLTAGE: 500V
R462 R468 = RES: RES MF ZERO OHM 1/10W -- 0603; AGILE_PN: 470-80866; CAD_APPROVED: Yes; FPLIST: RC0603_OV,RC0603,R603-X2,0603_CC,IND_0603HP_NSP,CC0603_OV_NSP; HEIGHT: 0.6MM; MFG_NAME01: WALSIN TECHNOLOGY CORP.; MFG_PN01: WR06X000PTL; ROHS: Yes; Temp Range: –55 °C to +155 °C
R471 = RES: RES MF 1.5K 1/16W 1% 0402; AGILE_PN: 470-80487; ASSY_NOTE: 470-76065; CAD_APPROVED: Yes; FPLIST: RC0402_25,RC0402_HD,0402_CC; HEIGHT: 0.4MM; MFG_NAME01: BOURNS; MFG_PN01: CR0402-FX-1501GLF; PRIORITY_PN: 006-00654; ROHS: Yes; ROOM: RGMII_PHY; TOLERANCE: 1%
TP135 = T_POINT_R: TEST POINT PAD .035 SMT, no part to order; AGILE_PN: 510-75618; ASSY_OPT: DNP; CAD_APPROVED: Yes; HEIGHT: 0.1MM; ROHS: Yes
U35 = RTL8211FDI-40P: IC XCVR ETH INTEGRATED 10/100/1000MBPS RGMII 3.3V/2.5V/1.8V QFN40; 3D_Mechanical_Footprint_File: http://fcl.am.freescale.net/ALLEGRO/step/qfn40_0p4_5x5mm.STEP; AGILE_PN: TMP-CIP-10596; CAD_APPROVED: Yes; HEIGHT: 0.9MM; MFG_NAME01: REALTEK SEMICONDUCTOR; PRE_APN: 312-83499; Package Size: QFN40; ROHS: Yes; Temp Range: -40  °C  +85 °C
U37 U38 = DIODE_ESD_4CH_10P_A: DIODE ARRAY ESD 3.3V 5A DFN2510A-10; 3D_Mechanical_Footprint_File: http://fcl.am.freescale.net/ALLEGRO/step/xson10_0p5_1p1x2p6mm.step; AGILE_PN: 480-78961; CAD_APPROVED: Yes; HEIGHT: 0.5; MFG_NAME01: NEXPERIA; MFG_PN01: PUSB3FR4Z; Package Size: 2.5 mm x 1 mm x 0.5 mm; Temp Range: -40°C to 85°C
Y2 = XTAL_13: XTAL 25MHZ FIXED -- SMT; AGILE_PN: 230-76732; CAD_APPROVED: Yes; HEIGHT: 0.55; MFG_NAME01: TXC CORP; MFG_PN01: 8Z 25.000; ROHS: Yes

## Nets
5V_PG: R323.2 TP151.1(Pin1) U39.1(PGOOD)
GND: BH1.1 BH2.1 BH4.1 BH5.1 C94.2 C95.2 C112.2 C121.2 C125.1 C127.2 C141.2 C142.2 C143.2 C148.2 C150.2 C154.2 C156.2 C159.2 C160.2 C163.2 C164.2 C169.1 C170.2 C174.1 C175.2 C176.2 C182.2 C183.2 C187.1 C192.1 C193.2 C194.2 C195.2 C200.2 C262.2 C271.2 C275.2 C276.2 C277.2 C278.2 C279.2 C280.2 C281.2 C285.2 C291.2 C294.2 C295.2 C296.2 C301.2 C304.2 C312.1 C313.2 C314.2 C315.2 C317.2 D29.A(ANODE) GND12.1(Pin1) GND14.1(Pin1) GND16.1(Pin1) GND20.1(Pin1) GND21.1(Pin1) GND22.1(Pin1) GND25.1(Pin1) J12.A1(GND1) J12.A12(GND2) J12.B1(GND4) J12.B12(GND3) J12.SH1 J12.SH2 J12.SH3 J12.SH4 J13.A12(GND1) J13.B12(GND2) J13.SH1 J13.SH2 J13.SH3 J13.SH4 Q8.2(SOURCE) Q10.2(SOURCE) R245.2 R247.2 R254.2 R271.2 R294.2 R298.2 R299.2 R304.2 R309.1 R311.2 R321.2 R338.2 R340.1 R361.1 R367.1 R452.2 R453.2 R454.2 R455.2 R456.2 R457.2 R473.1 R474.2 TP3.1(Pin1) TP12.1(Pin1) TP28.1(Pin1) TP40.1(Pin1) TP75.1(Pin1) TP128.1(Pin1) U35.41(GND) U36.2(VSS) U37.3(GND1) U37.8(GND2) U38.3(GND1) U38.8(GND2) U39.3(AGND1) U39.4(PGND1) U39.5(PGND2) U39.6(PGND3) U39.7(PGND4) U39.8(PGND5) U39.25(AGND2) U39.33(AGND3) U45.C3(GND1) U45.D3(GND2) U45.E3(GND3) U46.3(GND) U47.A4(GND1) U47.B2(GND2) U47.B3(GND3) U47.B4(GND4) U47.B5(GND5) U48.5(SLV_ADDR) U48.17(GND) U49.17(GND) U51.B3(GND) U51.D3(SBUEN) U52.B3(GND) U52.D3(SBUEN) U55.B1(GND) U58.4(GND) Y2.2 Y2.4 ; also on sheet 1 2 3 7 8 9 13 17 18 19 20 21 22 23 24
GND_CHASSIS: C174.2 J9.10(GND) J9.SH1 J9.SH2 R361.2
VBUS_IN: C141.1 R283.1 TP152.1(Pin1) U39.14(VIN1) U39.15(VIN2) U39.16(VIN3) U39.17(VIN4) U39.23(VIN5) U39.35(VIN6) U45.A1(VINT1) U45.B1(VINT2) U45.C1(VINT3) U45.D1(VINT4)
VBUS_OVLO_TH: R311.1 R313.2 U45.B3(OVLO)
VCCO_5V: C304.1 R472.1 U39.21(VCC)
VDD_1V8: R91.1 R458.1 R471.1 ; also on sheet 2 7 19 22 23 24
VDD_3V3: C314.1 C315.1 L11.1 L14.1 R249.1 R274.1 R280.1 R330.1 R331.1 R373.1 R375.1 R477.1 R478.2 U48.3(VDD) U49.3(VDD) ; also on sheet 1 2 7 8 9 13 19 20 21 22 23 24
VDD_5V: C127.1 C192.2 C200.1 C312.2 R289.1 R479.1 TP185.1(Pin1) U36.5(VDD) U48.12(VCONN_IN) U49.12(VCONN_IN) U58.7(VOUT) ; also on sheet 21 23
BYPASS1: C187.2 U48.4(BYPASS)
DBG_ACC: TP154.1(Pin1) U48.9(DBG_ACC)
DCDC_5V: C142.1 C143.1 C154.1 C156.1 C168.1 C170.1 C173.2 C194.1 C317.1 R323.1 R341.1 R365.2 TP188.1(Pin1) U39.28(VOUT) U47.D2(V5V_1) U47.D3(V5V_5) U47.E2(V5V_2) U47.E3(V5V_6) U47.F2(V5V_3) U47.F3(V5V_7) U47.G2(V5V_4) U47.G3(V5V_8) U58.1(VIN) U58.3(VCC) U58.8(VIN_2) ; also on sheet 2 22
EN_SNK: R370.2 U47.F1(EN_SNK)
EN_SRC: R369.2 U47.G1(EN_SRC)
ENET1_MDC: R267.1 TP143.1(Pin1) ; also on sheet 20
ENET1_MDIO: R263.1 R471.2 TP140.1(Pin1) ; also on sheet 20
ENET1_nINT: R249.2 U35.31(~{INT}/~{PME}) ; also on sheet 20
ENET1_nRST: R274.2 TP144.1(Pin1) U35.12(~{PHYRST}) ; also on sheet 13
ENET1_RD0: R446.2 R455.1 TP83.1(Pin1) U35.25(RXD0/RXDLY) ; also on sheet 20
ENET1_RD1: R445.2 R454.1 U35.24(RXD1/TXDLY) ; also on sheet 20
ENET1_RD2: R444.2 R453.1 U35.23(RXD2/PLLOFF) ; also on sheet 20
ENET1_RD3: R443.2 R452.1 U35.22(RXD3/PHYAD0) ; also on sheet 20
ENET1_RX_CTL: R456.1 TP89.1(Pin1) U35.26(RXCTL/PHYAD2) ; also on sheet 20
ENET1_RXC: C262.1 R447.2 R457.1 TP84.1(Pin1) U35.27(RXC/PHYAD1) ; also on sheet 20
ENET1_TD0: TP137.1(Pin1) U35.18(TXD0) ; also on sheet 20
ENET1_TD1: U35.17(TXD1) ; also on sheet 20
ENET1_TD2: U35.16(TXD2) ; also on sheet 20
ENET1_TD3: U35.15(TXD3) ; also on sheet 20
ENET1_TX_CTL: TP134.1(Pin1) U35.19(TXCTL) ; also on sheet 20
ENET1_TXC: TP133.1(Pin1) U35.20(TXC) ; also on sheet 20
ETH1_10/100M_Link/Active: J9.13 R305.1
ETH1_1000M_Link/Active: J9.11 R303.1 R304.1
ETH1_AVDD1V0: C285.1 C291.1 C295.1 C296.1 R468.2 U35.3(AVDD09_1) U35.8(AVDD09_2) U35.38(AVDD09_3)
ETH1_AVDD3V3: C294.1 C301.1 L11.2 U35.11(AVDD33_1) U35.40(AVDD33_2)
ETH1_CLK125_OUT: TP138.1(Pin1) U35.35(CLKOUT)
ETH1_CT: C148.1 J9.1(CT)
ETH1_DVDD1V0: C276.1 C277.1 R462.2 U35.21(DVDD09)
ETH1_DVDD3V3: C280.1 C281.1 L14.2 R246.1 R253.1 R303.2 U35.29(DVDD33)
ETH1_LED0/CFG_EXT: R246.2 R247.1 R305.2 U35.32(CFG_EXT/LED0)
ETH1_LED1/CFGLDO0: C94.1 J9.14 R245.1 U35.33(CFG_LDO0/LED1)
ETH1_LED2/CFGLDO1: C95.1 J9.12 R253.2 R254.1 U35.34(CFG_LDO1/LED2)
ETH1_TRX0_N: J9.3(TRD1-) U35.2(MDIN0) U37.2(CH2) U37.9(NC3)
ETH1_TRX0_P: J9.2(TRD1+) U35.1(MDIP0) U37.1(CH1) U37.10(NC4)
ETH1_TRX1_N: J9.5(TRD2-) U35.5(MDIN1) U37.5(CH4) U37.6(NC1)
ETH1_TRX1_P: J9.4(TRD2+) U35.4(MDIP1) U37.4(CH3) U37.7(NC2)
ETH1_TRX2_N: J9.7(TRD3-) U35.7(MDIN2) U38.2(CH2) U38.9(NC3)
ETH1_TRX2_P: J9.6(TRD3+) U35.6(MDIP2) U38.1(CH1) U38.10(NC4)
ETH1_TRX3_N: J9.9(TRD4-) U35.10(MDIN3) U38.5(CH4) U38.6(NC1)
ETH1_TRX3_P: J9.8(TRD4+) U35.9(MDIP3) U38.4(CH3) U38.7(NC2)
ETH1_VDD1V0: C271.1 C275.1 R462.1 R468.1 TP135.1(TP) U35.30(LDO_OUT)
ETH1_VDDIO: C278.1 C279.1 R443.1 R444.1 R445.1 R446.1 R447.1 R458.2 U35.28(DVDD_RG)
ETH1_XTALI: C112.1 R264.2 U35.36(XTAL_IN) Y2.3
ETH1_XTALO: C121.1 R264.1 U35.37(XTAL_OUT/_EXT_CLK) Y2.1
FRS_EN: U47.B6(FRS_EN) U48.1(FRS_EN)
I2C1_SCL: R366.2 ; also on sheet 13 20 22
I2C1_SDA: R363.2 ; also on sheet 13 20 22
ILIM_5V_VBUS: TP171.1(Pin1) U48.6(ILIM_5V_VBUS)
LD_I2C_SCL: R368.1 U47.B1(SCL)
LD_I2C_SDA: R364.1 R475.1 U47.C1(SDA)
LD_nFLT: R329.1 R330.2 U48.11(FAULT_N)
LD_nINT: R329.2 U47.D1(~{INT})
PD_BYPASS: C169.2 U49.4(BYPASS)
PD_DBG_ACC: TP170.1(Pin1) U49.9(DBG_ACC)
PD_EN_SINK: R339.1 U49.2(EN_SNK1)
PD_EN_SRC: TP165.1(Pin1) U49.16(EN_SRC)
PD_FRS_EN: TP157.1(Pin1) U49.1(FRS_EN)
PD_ILIM_5V_VBUS: TP156.1(Pin1) U49.6(ILIM_5V_VBUS)
PD_LD_nFLT: R376.1 U49.11(FAULT_N)
PD_USB_CC1: U49.13(CC1) U52.A2(CC1)
PD_USB_CC2: U49.14(CC2) U52.B2(CC2) U52.C1(CON_SBU1) U52.C2(SBU1)
PD_VBUS_PG: Q10.1(GATE) R374.2 TP153.1(Pin1) U45.A2(ACK)
PMIC_ON_REQ: R476.1 ; also on sheet 3 7 19
REG_FEQ: R309.2 U39.29(RT)
REG_MODE: R472.2 R473.2 U39.2(MODE)
REG_ST: C125.2 U39.24(CSS/TRK)
TCPC1_nINT: R331.2 U48.10(ALERT_N) ; also on sheet 13
TCPC_nINT: R373.2 TP169.1(Pin1) U49.10(ALERT_N) ; also on sheet 13
USB1_CC1: U48.13(CC1) U51.A2(CC1)
USB1_CC2: U48.14(CC2) U51.B2(CC2) U51.C1(CON_SBU1) U51.C2(SBU1)
USB1_DN: U55.C1(CH1_OUT+) ; also on sheet 20
USB1_DP: U55.C2(CH1_OUT-) ; also on sheet 20
USB1_ID: R91.2 TP26.1(Pin1) ; also on sheet 20
USB1_VBUS_3V3: R280.2 U36.1(VOUT) ; also on sheet 20
USB1_VBUS_IN: C181.2 TP167.1(Pin1) U47.C6(VCHG1) U47.D6(VCHG2) U47.E6(VCHG3) U47.F6(VCHG4) U47.G6(VCHG5)
USB_CC1_PD: J13.A5(CC1) R381.1 TP175.1(Pin1)
USB_CC1_PD_OVP: R383.2 U52.A1(CON_CC1)
USB_CC2_PD: J13.B5(CC2) R380.1 TP176.1(Pin1)
USB_CC2_PD_OVP: R385.2 U52.B1(CON_CC2)
USB_I2C_SCL: R359.2 R366.1 R368.2 U49.8(I2C_SCL) ; also on sheet 21
USB_I2C_SDA: R362.2 R363.1 R364.2 U49.7(I2C_SDA) ; also on sheet 21
USB_PD_VBUS: F1.1 J13.A9(VBUS1) J13.B9(VBUS2)
USB_PD_VBUS_F: C193.1 D25.A F1.2 R313.1 R319.1 U45.B2(VBUS1) U45.C2(VBUS2) U45.D2(VBUS3) U45.E1(VBUS4) U45.E2(VBUS5) U49.15(VBUS)
USBC_CC1: J12.A5(CC1) TP173.1(Pin1) U51.A1(CON_CC1)
USBC_CC2: J12.B5(CC2) TP174.1(Pin1) U51.B1(CON_CC2)
USBC_DN: J12.A7(DN1) J12.B7(DN2) U55.A1(CH1_IN+)
USBC_DP: J12.A6(DP1) J12.B6(DP2) U55.A2(CH1_IN-)
USBC_EN_SNK1: R370.1 U48.2(EN_SNK1)
USBC_EN_SRC1: R369.1 U48.16(EN_SRC)
USBC_I2C_SCL: R359.1 U48.8(I2C_SCL)
USBC_I2C_SDA: R362.1 U48.7(I2C_SDA)
USBC_VBUS: F2.1 J12.A4(VBUS1) J12.A9(VBUS2) J12.B4(VBUS4) J12.B9(VBUS3)
USBC_VBUS_F: C150.1 D24.A F2.2 R288.1 R294.1 U47.C2(VBUS1) U47.C3(VBUS2) U47.C4(VBUS3) U47.C5(VBUS4) U47.D4(VBUS5) U47.D5(VBUS6) U47.E4(VBUS7) U47.E5(VBUS8) U47.F4(VBUS9) U47.F5(VBUS10) U47.G4(VBUS11) U47.G5(VBUS12) U48.15(VBUS)
VLDO1_3V3: C182.1 U47.A5(VLDO)
VLDO_3V3: C175.1 C176.1 C195.1 C313.1 R320.1 R374.1 U46.1(OUT) U47.A1(VDD) U51.A3(VSYS) U52.A3(VSYS) ; also on sheet 21
VSYS_5V_COMP: C160.1 R317.1 U39.30(COMP)
VSYS_5V_FB: C168.2 R341.2 R474.1 U39.31(FB)
VSYS_EN: R283.2 U39.26(CE)
N117403125: Q8.3(DRAIN) R319.2 R320.2 U45.A3(\\~{E}N)
N117403218: R383.1 SW5.2(COMMON1)
N117403229: R381.2 SW5.3(NO1)
N117403272: R385.1 SW5.5(COMMON2)
N117403287: R380.2 SW5.6(NO2)
N117403318: TP172.1(Pin1) U52.C3(FLAG)
N117403325: C163.1 Q8.1(GATE) R321.1 R339.2
N117403441: Q10.3(DRAIN) R375.2 R376.2
N117403643: R338.1 U49.5(SLV_ADDR)
N117404021: C173.1 R360.1 U39.27(SENSE)
N117404068: R479.2 U58.5(BLEED)
N117404089: R478.1 U58.6(PG)
N117404099: C306.1 U39.19(BST)
N117404161: R476.2 R477.2 U58.2(EN)
N117404173: C306.2 L12.1 U39.9(LX1) U39.10(LX2) U39.11(LX3) U39.12(LX4) U39.34(LX5)
N117404204: L12.2 R360.2 R365.1
N117404484: C159.1 R317.2
N117446518: R289.2 R299.1 U36.4(IN_INV)
N117446570: D29.C(CATHODE) R288.2 R298.1 U36.3(IN_NON-INV)
N117446967: C181.1 U47.A6(CAP2)
N117446993: C183.1 U47.A3(CAP1)
N117447048: R367.2 U47.A2(~{EN})
N117447064: R340.2 R475.2 U47.E1(ADDR)
N117447556: C164.1 D24.C D25.C U46.2(IN)
N117447734: TP166.1(Pin1) U51.C3(FLAG)
N117451840: R263.2 U35.14(MDIO)
N117451860: R267.2 U35.13(MDC)
N117452169: R271.1 U35.39(RSET)

Not connected (* = marked no-connect by the designer): J12 A2(SSTXP1)* A3(SSTXN1)* A8(SBU1)* A10(SSRXN2)* A11(SSRXP2)* B2(SSTXP2)* B3(SSTXN2)* B8(SBU2)* B10(SSRXN1)* B11(SSRXP1)*; SW5 1(NC1)* 4(NC2)*; U39 13(NC1)* 18(NC2)* 20(NC3)* 22(NC4)* 32(CLKOUT)*; U51 D1(CON_SBU2)* D2(SBU2)*; U52 D1(CON_SBU2)* D2(SBU2)*

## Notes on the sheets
sheet 10
- RGMII 10/100/1000Mbps Ethernet
- 10/100Mb/s Link / Active
- Z:100 OHM
- Z:100 OHM
- O/LI/PD
- LED0: 10Mbps
- O/LI/PU
- LED1: 100Mbps
- O/LI/PD
- LED2: 1000Mbps
- 1 Gb/s Link / Active
- 3.3V IO
- 3.3V IO
- Ethernet IO Voltage,
  default = 1.8 V
  Internal.
- ESD protection
- Power-on Strapping Pins CFG
- RGMII Power Source
- CFG_EXT
- CFG_LDO[1:0]
- External 3.3V
- 1
- 00
- External 2.5V
- 1
- 01
- External 1.8V
- 1
- 10
- External 1.5V
- 1
- 11
- Internal 2.5V
- 0
- 01
- Internal 1.8V(Default)
- 0
- 10
- Internal 1.5V
- 0
- 11
- PHY Address
- PHYAD[2:0]
- 1
- 001
- 2
- 010
- Close to RTL8211
- Close to I.MX91
- Close to signal test points
- # Pull-up for additional 2ns delay to
  TXC/RXC for data latching.
- # Pull-up to disable PLL @ ALDPS mode.
- EMI Filter Reserved
sheet 11
- USB1 TYPE-C
- For discharge
- # VBUS > 3.7V ->  H
- # VBUS detect >=3.7V is a requirement from USB Type-C Functional Test Specification.
- # For Non Type-C case, VBUS input is usually 5V, the comparator circuit can be removed, and VBUS input
  can be directly connected to i.MX91 USBx_VBUS pin through a 30K 1% serial resistor for cost saving.
- VBUS DET
- De-bounce
- PWR SW OFF
- PWR SW ON
- Reboot
- #Set to 3.4A I2C CTRL
- # Use Always On Power(with VBUS), aviod entering Dead Battery Mode.
- OD
- I/OD
- #I2C ADDR: 0b'1110001x
- O
- O
- #default "L"
- SLV_ADDR
- Dev ADDR
- O
- GND
- 1010000x
- 10 K pull-up to BYPASS
- 1010001x
- O/OD
- 100 K pull-up to BYPASS
- Unconnected
- 1010010x
- 1010011x
- default "UFP" mode
- #I2C ADDR: 0b'1010000X
- Always ON LDO
- Z:90 OHM
- Z:90 OHM
- # This LDO is used for preventing the Ld SW NX20P3483UK enter into
  dead battery mode.
- #C1 C2 PIN used for layout convenient
- CC OVP
sheet 12
- USB TYPE-C PD
- USB C
  PD
- R1
- R2
- CC OVP
- Vovlo= Vth*(R1 + R2)/R2
- OVLO=0, OVP threshold=23V
- #C1 C2 PIN used for layout convenient
- SYS PWR SW
- # Control CC for Type-C PD power on/off control
- SW
- PD ADAPTER
- 1-2/4-5
- OFF <Default>
- 3-2/6-5
- ON
- I/OD
- O
- O
- SLV_ADDR
- Dev ADDR
- #default "L"
- 10 K pull-up to BYPASS
- GND
- 1010000x
- 1010001x
- O
- Unconnected
- 1010010x
- 100 K pull-up to BYPASS
- 1010011x
- O/OD
- default "UFP" mode
- # I2C ADDR: 0b'1010010X
- SYSTEM POWER
- PERIPHERAL POWER
- #bleeder
- # 5.2V/8A
- LD SW
- VIN:  0.5-13.5V
  VCC: 3.0-5.5V
  Imax:10.5A
- EN PD: 76-124K
  EN > 2.0V
- R1
- Vout = (R1+R2) * Vfb(0.64V) / R2
- Css=1nF Tss=0.5ms
  Css=4.7nF Tss=1.6ms
  Css=33nF Tss=10ms
- R2
- RT=32K Freq=1MHz
  RT=66K Freq=500KHz
  RT=135K Freq=250KHz
- GND TESTLOOP
- GND TP
- SCREW HOLE
- TOP Layer
- BOTTOM Layer
